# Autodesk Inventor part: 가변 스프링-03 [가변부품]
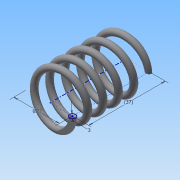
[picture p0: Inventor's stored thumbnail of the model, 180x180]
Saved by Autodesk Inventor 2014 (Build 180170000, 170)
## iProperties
Created: 2015-09
Part Number: 가변 스프링-03 [가변부품]
Material: 강철, 탄소
Document SubType Name: Modeling
Designer: study
Density: 7.87 g/cm^3
Appearance: 반연마
Mass: 18.7944 g
Surface Area: 32.46 cm^2
Volume: 2.38811 cm^3
Author: study
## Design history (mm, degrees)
sketch "스케치1"
  geometry: L1 (0, 0)-(11, 0); L2 (11, 0)-(11, 28.411); L3 (11, 28.411)-(0, 28.411); L4 (0, 28.411)-(0, 0); C1 r 1.5 at (11, 0)
  constraints: 8 end point, 2 parallel, 1 centre point, 1 coincident, 1 horizontal, 1 perpendicular
  dimensions: "d0" = 28.4112 distance of L1.end L2.end (derived); "d1" = 22 diameter of L2 L4; "d2" = 3 diameter of C1
feature "코일1" sketch "스케치1" pitch "d3" = 10; turns "d5" = 5; dims "d4" = 28.4112 (= d0), "d6" = 0, angle "d7" = 90 deg, angle "d8" = 90 deg, "d9" = 0, "d10" = 0
node "작업 평면1"
sketch "스케치2"
  geometry: L1 (-12.5, 0)-(-9.5, 0) reference; 1 further point
  constraints: 1 horizontal alignment
extrude "돌출1" cut sketch "스케치2" stored distance "d12" = 10; taper "d13" = 0 deg
node "작업 평면2"
sketch "스케치3"
  geometry: L1 (-9.5, 0)-(-12.5, 0) reference; 1 further point
  constraints: 1 horizontal alignment
extrude "돌출2" cut sketch "스케치3" stored distance "d15" = 10; taper "d16" = 0 deg
node "솔리드1"
node "절단 모서리 투영1"
node "절단 모서리 투영2"
other parameters: "d11" = 0, "d14" = 28.4112 (= d0)
